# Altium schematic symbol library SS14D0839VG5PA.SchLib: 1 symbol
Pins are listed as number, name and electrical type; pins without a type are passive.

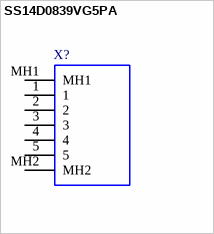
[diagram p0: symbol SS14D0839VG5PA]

## SS14D0839VG5PA
designator X?
Slide Switches; Manufacturer_Name: C & K COMPONENTS; Geometry.Height: 6.7mm
footprint SS14D0839VG5PA
pins: 1, 2, 3, 4, 5, MH1, MH2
